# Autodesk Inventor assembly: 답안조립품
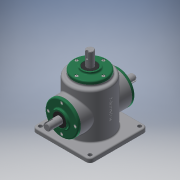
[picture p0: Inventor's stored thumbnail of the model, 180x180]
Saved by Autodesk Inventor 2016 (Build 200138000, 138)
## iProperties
Created: 2019-08
Part Number: 답안조립품
Material: 일반
Document SubType Name: Assembly
Designer: user
Author: user
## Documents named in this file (16)
- D:\490823V1008\답안조립품.iam
- D:\490823V1008\본체.ipt
- D:\490823V1008\메인 베벨기어.ipt
- D:\490823V1008\메인 축.ipt
- 메인 축.ipt
- D:\490823V1008\베어링 6203.ipt
- D:\490823V1008\볼트 M4.ipt
- 볼트 M4.ipt
- D:\490823V1008\서브 베벨기어.ipt
- D:\490823V1008\서브 축.ipt
- 서브 축.ipt
- D:\490823V1008\오일 실.ipt
- 오일 실.ipt
- D:\490823V1008\커버.ipt
- D:\490823V1008\키 4x4.ipt
- D:\490823V1008\키 5x5.ipt
